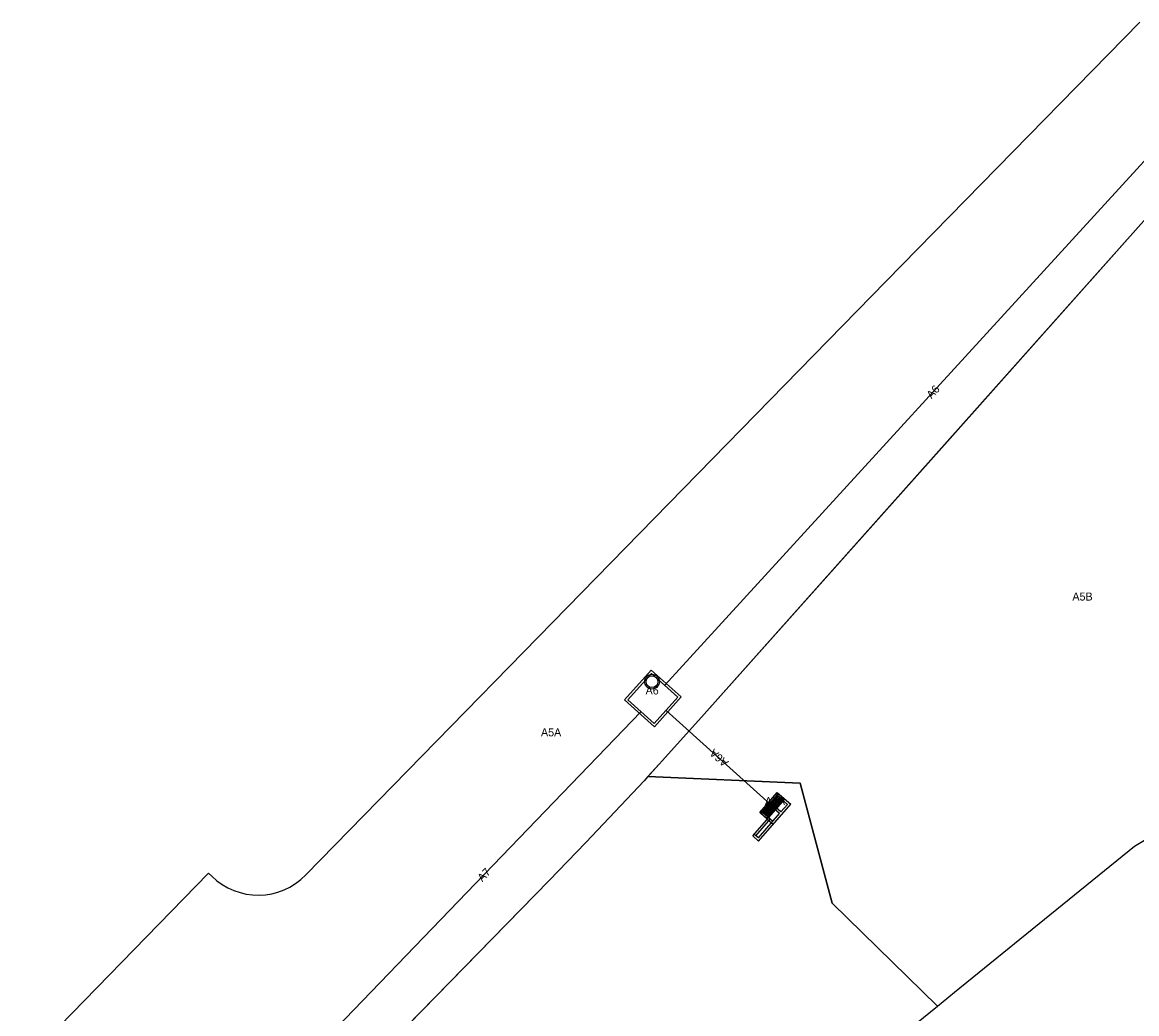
# Model space of a CAD drawing. Extents: x 2252703 to 2264864, y 13787568 to 13790989.
# Drawn here: x 2253981.3 to 2254231.9, y 13789915.2 to 13790138.2 of the extents above; entities that cross this region are included whole.
import ezdxf

# ---------------------------------------------------------------- set-up
doc = ezdxf.new("R2010")
doc.units = 0
for name, color, linetype in [('D_BOXES_1', 7, 'Continuous'), ('D_DRAIN_MISC', 7, 'Continuous'), ('D_DRAIN_NOTES_1', 7, 'Continuous'), ('D_DRN_AREA_X', 7, 'Continuous'), ('D_INLET_1', 7, 'Continuous'), ('D_PIPES_1', 7, 'Continuous')]:
    doc.layers.add(name, color=color, linetype=linetype)

msp = doc.modelspace()

# ---------------------------------------------------------------- linework, layer by layer
at = {"layer": 'D_BOXES_1'}
for p, q in [((2254125.73, 13789989.12), (2254246.59, 13790121.36)), ((2254049.99, 13789910), (2254120.39, 13789983.17))]:
    msp.add_line(p, q, dxfattribs=at)
at = {"layer": 'D_DRAIN_MISC'}
for p, q in [((2254125.73, 13789989.12), (2254125.73, 13789989.12)), ((2254120.08, 13789988.81), (2254120.08, 13789988.81)), ((2254123.06, 13789986.14), (2254123.06, 13789986.14)), ((2254120.39, 13789983.17), (2254120.39, 13789983.17)), ((2254126.03, 13789983.47), (2254126.03, 13789983.47)), ((2254149.44, 13789962.4), (2254149.44, 13789962.4)), ((2254152.21, 13789963.3), (2254152.21, 13789963.3)), ((2254148.93, 13789959.53), (2254148.93, 13789959.53)), ((2254150.76, 13789961.25), (2254150.76, 13789961.25)), ((2254151.7, 13789960.43), (2254151.7, 13789960.43))]:
    msp.add_line(p, q, dxfattribs=at)
at = {"layer": 'D_DRN_AREA_X'}
for p, q in [((2254232.56, 13790138.24), (2254175.55, 13790079.98)), ((2254134.63, 13789982.58), (2254234.65, 13790094.92)), ((2254234.65, 13790094.92), (2254189.9, 13790044.65)), ((2254189.9, 13790044.65), (2254134.63, 13789982.58)), ((2254134.63, 13789982.58), (2254125.24, 13789972.22)), ((2254231.38, 13789952.91), (2254269.1, 13789975.9)), ((2254125.24, 13789972.22), (2254121.96, 13789968.61)), ((2254121.09, 13789967.64), (2254108.02, 13789953.74)), ((2254121.96, 13789968.61), (2254121.09, 13789967.64)), ((2254121.96, 13789968.61), (2254156.18, 13789967.12)), ((2254156.18, 13789967.12), (2254121.96, 13789968.61)), ((2254156.18, 13789967.12), (2254163.36, 13789940.11)), ((2254163.36, 13789940.11), (2254156.18, 13789967.12)), ((2254108.02, 13789953.74), (2254099.77, 13789945.21)), ((2254190.88, 13789920.06), (2254231.38, 13789952.91)), ((2254023.17, 13789946.84), (2253981.29, 13789903.85)), ((2254023.87, 13789946.16), (2254023.17, 13789946.84)), ((2254099.77, 13789945.21), (2254058.27, 13789902.74)), ((2254163.36, 13789940.11), (2254187.06, 13789916.96)), ((2254187.06, 13789916.96), (2254163.36, 13789940.11)), ((2254187.06, 13789916.96), (2254190.88, 13789920.06)), ((2254156.89, 13789892.48), (2254187.06, 13789916.96))]:
    msp.add_line(p, q, dxfattribs=at)
for points in [[(2254175.55, 13790079.98), (2254126.68, 13790029.98), (2254045.04, 13789946.44)], [(2254108.02, 13789953.74), (2254121.09, 13789967.64), (2254134.63, 13789982.58)], [(2254025.79, 13789869.5), (2254099.77, 13789945.21), (2254108.02, 13789953.74)]]:
    msp.add_lwpolyline(points, dxfattribs=at)
msp.add_arc((2254034.32, 13789956.92), 15, 225.8716, 315.6588, dxfattribs=at)
at = {"layer": 'D_INLET_1'}
for p, q in [((2254116.7, 13789985.8), (2254122.72, 13789992.5)), ((2254117.41, 13789985.84), (2254122.76, 13789991.79)), ((2254122.72, 13789992.5), (2254129.41, 13789986.48)), ((2254122.76, 13789991.79), (2254128.71, 13789986.44)), ((2254128.71, 13789986.44), (2254123.36, 13789980.49)), ((2254129.41, 13789986.48), (2254123.4, 13789979.79)), ((2254123.4, 13789979.79), (2254116.7, 13789985.8)), ((2254123.36, 13789980.49), (2254117.41, 13789985.84)), ((2254147.09, 13789960.46), (2254151.02, 13789964.99)), ((2254147.1, 13789960.46), (2254151.03, 13789964.99)), ((2254147.36, 13789960.77), (2254150.76, 13789964.68)), ((2254147.41, 13789960.18), (2254151.34, 13789964.72)), ((2254147.8, 13789960.51), (2254151.07, 13789964.29)), ((2254151.03, 13789964.47), (2254149.34, 13789962.51)), ((2254151.04, 13789964.4), (2254149.4, 13789962.51)), ((2254149.42, 13789962.52), (2254151.04, 13789964.38)), ((2254149.51, 13789962.66), (2254150.99, 13789964.37)), ((2254150.73, 13789963.86), (2254150.86, 13789964.02)), ((2254151.02, 13789963.61), (2254150.73, 13789963.86)), ((2254151, 13789964.43), (2254150.74, 13789964.66)), ((2254150.79, 13789964.69), (2254151.2, 13789964.69)), ((2254151.15, 13789963.77), (2254150.86, 13789964.02)), ((2254150.92, 13789964.09), (2254151.06, 13789964.24)), ((2254151.21, 13789963.84), (2254150.92, 13789964.09)), ((2254151.02, 13789964.99), (2254154.05, 13789962.37)), ((2254151.03, 13789964.47), (2254152.32, 13789963.35)), ((2254151.04, 13789964.4), (2254152.25, 13789963.35)), ((2254151.04, 13789964.38), (2254152.23, 13789963.35)), ((2254151.06, 13789964.24), (2254151.35, 13789963.99)), ((2254151.07, 13789964.43), (2254151.26, 13789964.66)), ((2254151.07, 13789964.29), (2254153.34, 13789962.32)), ((2254151.12, 13789964.39), (2254151.31, 13789964.61)), ((2254151.21, 13789963.84), (2254151.35, 13789963.99)), ((2254151.24, 13789964.67), (2254152.53, 13789963.55)), ((2254151.29, 13789963.77), (2254151.43, 13789963.92)), ((2254151.43, 13789963.92), (2254151.72, 13789963.67)), ((2254145.52, 13789955.21), (2254152.72, 13789963.52)), ((2254146.84, 13789954.06), (2254154.05, 13789962.37)), ((2254147.61, 13789960.53), (2254149.31, 13789962.48)), ((2254147.68, 13789960.53), (2254149.32, 13789962.42)), ((2254149.32, 13789962.4), (2254147.7, 13789960.53)), ((2254147.7, 13789960.58), (2254149.18, 13789962.29)), ((2254148.56, 13789961.36), (2254148.42, 13789961.2)), ((2254148.85, 13789961.11), (2254148.56, 13789961.36)), ((2254148.75, 13789961.58), (2254148.62, 13789961.43)), ((2254148.91, 13789961.18), (2254148.62, 13789961.43)), ((2254148.73, 13789959.17), (2254151.63, 13789962.51)), ((2254149.04, 13789961.33), (2254148.75, 13789961.58)), ((2254148.95, 13789961.81), (2254148.81, 13789961.65)), ((2254149.1, 13789961.4), (2254148.81, 13789961.65)), ((2254148.89, 13789959.47), (2254150.53, 13789961.37)), ((2254148.89, 13789959.49), (2254150.51, 13789961.36)), ((2254148.9, 13789959.41), (2254150.59, 13789961.37)), ((2254149.04, 13789961.33), (2254148.91, 13789961.18)), ((2254149.23, 13789961.56), (2254148.95, 13789961.81)), ((2254149.14, 13789962.03), (2254149.01, 13789961.88)), ((2254149.3, 13789961.63), (2254149.01, 13789961.88)), ((2254149.23, 13789961.56), (2254149.1, 13789961.4)), ((2254149.43, 13789961.78), (2254149.14, 13789962.03)), ((2254149.32, 13789961.49), (2254149.18, 13789961.33)), ((2254149.47, 13789961.08), (2254149.18, 13789961.33)), ((2254149.33, 13789962.26), (2254149.2, 13789962.1)), ((2254149.49, 13789961.85), (2254149.2, 13789962.1)), ((2254151.54, 13789960.24), (2254149.21, 13789962.26)), ((2254149.43, 13789961.78), (2254149.3, 13789961.63)), ((2254149.31, 13789962.48), (2254150.59, 13789961.37)), ((2254149.32, 13789962.42), (2254150.53, 13789961.37)), ((2254149.32, 13789962.4), (2254150.51, 13789961.36)), ((2254149.61, 13789961.23), (2254149.32, 13789961.49)), ((2254149.33, 13789962.26), (2254149.62, 13789962.01)), ((2254149.34, 13789962.51), (2254150.62, 13789961.4)), ((2254149.51, 13789961.71), (2254149.38, 13789961.56)), ((2254149.67, 13789961.3), (2254149.38, 13789961.56)), ((2254149.4, 13789962.51), (2254150.61, 13789961.46)), ((2254149.42, 13789962.52), (2254150.61, 13789961.48)), ((2254149.62, 13789962.01), (2254149.49, 13789961.85)), ((2254149.8, 13789961.46), (2254149.51, 13789961.71)), ((2254151.87, 13789960.62), (2254149.54, 13789962.64)), ((2254149.56, 13789962.52), (2254149.69, 13789962.67)), ((2254149.56, 13789962.52), (2254149.85, 13789962.27)), ((2254149.71, 13789961.94), (2254149.57, 13789961.78)), ((2254149.86, 13789961.53), (2254149.57, 13789961.78)), ((2254149.8, 13789961.46), (2254149.67, 13789961.3)), ((2254149.98, 13789962.42), (2254149.69, 13789962.67)), ((2254149.71, 13789961.94), (2254150, 13789961.68)), ((2254149.88, 13789961.39), (2254149.75, 13789961.23)), ((2254149.76, 13789962.74), (2254149.89, 13789962.9)), ((2254150.04, 13789962.49), (2254149.76, 13789962.74)), ((2254149.85, 13789962.27), (2254149.98, 13789962.42)), ((2254150, 13789961.68), (2254149.86, 13789961.53)), ((2254150.17, 13789961.14), (2254149.88, 13789961.39)), ((2254150.18, 13789962.64), (2254149.89, 13789962.9)), ((2254149.93, 13789962.2), (2254150.06, 13789962.35)), ((2254149.93, 13789962.2), (2254150.22, 13789961.94)), ((2254150.08, 13789961.61), (2254149.94, 13789961.46)), ((2254150.23, 13789961.21), (2254149.94, 13789961.46)), ((2254149.95, 13789962.97), (2254150.08, 13789963.12)), ((2254150.24, 13789962.71), (2254149.95, 13789962.97)), ((2254150.04, 13789962.49), (2254150.18, 13789962.64)), ((2254150.36, 13789962.1), (2254150.06, 13789962.35)), ((2254150.37, 13789962.87), (2254150.08, 13789963.12)), ((2254150.08, 13789961.61), (2254150.37, 13789961.36)), ((2254150.13, 13789962.42), (2254150.26, 13789962.57)), ((2254150.42, 13789962.17), (2254150.13, 13789962.42)), ((2254150.14, 13789963.19), (2254150.28, 13789963.34)), ((2254150.43, 13789962.94), (2254150.14, 13789963.19)), ((2254150.22, 13789961.94), (2254150.36, 13789962.1)), ((2254150.23, 13789961.21), (2254150.37, 13789961.36)), ((2254150.24, 13789962.71), (2254150.37, 13789962.87)), ((2254150.55, 13789962.32), (2254150.26, 13789962.57)), ((2254150.57, 13789963.09), (2254150.28, 13789963.34)), ((2254150.3, 13789961.87), (2254150.44, 13789962.03)), ((2254150.3, 13789961.87), (2254150.59, 13789961.62)), ((2254150.32, 13789962.64), (2254150.45, 13789962.8)), ((2254150.61, 13789962.39), (2254150.32, 13789962.64)), ((2254150.34, 13789963.42), (2254150.47, 13789963.57)), ((2254150.63, 13789963.16), (2254150.34, 13789963.42)), ((2254150.42, 13789962.17), (2254150.55, 13789962.32)), ((2254150.43, 13789962.94), (2254150.57, 13789963.09)), ((2254150.73, 13789961.77), (2254150.44, 13789962.03)), ((2254150.75, 13789962.54), (2254150.45, 13789962.8)), ((2254150.76, 13789963.32), (2254150.47, 13789963.57)), ((2254150.5, 13789962.1), (2254150.63, 13789962.25)), ((2254150.79, 13789961.85), (2254150.5, 13789962.1)), ((2254150.52, 13789962.87), (2254150.65, 13789963.02)), ((2254150.81, 13789962.62), (2254150.52, 13789962.87)), ((2254150.53, 13789963.64), (2254150.67, 13789963.79)), ((2254150.82, 13789963.39), (2254150.53, 13789963.64)), ((2254150.73, 13789961.77), (2254150.59, 13789961.62)), ((2254152.25, 13789963.35), (2254150.61, 13789961.46)), ((2254152.23, 13789963.35), (2254150.61, 13789961.48)), ((2254150.61, 13789962.39), (2254150.75, 13789962.54)), ((2254152.32, 13789963.35), (2254150.62, 13789961.4)), ((2254150.63, 13789963.16), (2254150.76, 13789963.32)), ((2254150.92, 13789962), (2254150.63, 13789962.25)), ((2254150.94, 13789962.77), (2254150.65, 13789963.02)), ((2254150.96, 13789963.54), (2254150.67, 13789963.79)), ((2254150.69, 13789962.32), (2254150.83, 13789962.47)), ((2254150.98, 13789962.07), (2254150.69, 13789962.32)), ((2254150.71, 13789963.09), (2254150.84, 13789963.25)), ((2254151, 13789962.84), (2254150.71, 13789963.09)), ((2254150.92, 13789962), (2254150.79, 13789961.85)), ((2254150.81, 13789962.62), (2254150.94, 13789962.77)), ((2254150.82, 13789963.39), (2254150.96, 13789963.54)), ((2254151.12, 13789962.22), (2254150.83, 13789962.47)), ((2254151.14, 13789962.99), (2254150.84, 13789963.25)), ((2254150.89, 13789962.55), (2254151.02, 13789962.7)), ((2254151.18, 13789962.29), (2254150.89, 13789962.55)), ((2254150.91, 13789963.32), (2254151.04, 13789963.47)), ((2254151.2, 13789963.06), (2254150.91, 13789963.32)), ((2254151.12, 13789962.22), (2254150.98, 13789962.07)), ((2254151, 13789962.84), (2254151.14, 13789962.99)), ((2254151.02, 13789963.61), (2254151.15, 13789963.77)), ((2254151.31, 13789962.45), (2254151.02, 13789962.7)), ((2254151.33, 13789963.22), (2254151.04, 13789963.47)), ((2254151.08, 13789962.77), (2254151.22, 13789962.92)), ((2254151.37, 13789962.52), (2254151.08, 13789962.77)), ((2254151.1, 13789963.54), (2254151.23, 13789963.7)), ((2254151.39, 13789963.29), (2254151.1, 13789963.54)), ((2254151.31, 13789962.45), (2254151.18, 13789962.29)), ((2254151.2, 13789963.06), (2254151.33, 13789963.22)), ((2254151.51, 13789962.67), (2254151.22, 13789962.92)), ((2254151.53, 13789963.44), (2254151.23, 13789963.7)), ((2254151.28, 13789962.99), (2254151.41, 13789963.15)), ((2254151.57, 13789962.74), (2254151.28, 13789962.99)), ((2254151.59, 13789963.51), (2254151.29, 13789963.77)), ((2254151.51, 13789962.67), (2254151.37, 13789962.52)), ((2254151.39, 13789963.29), (2254151.53, 13789963.44)), ((2254151.7, 13789962.9), (2254151.41, 13789963.15)), ((2254151.47, 13789963.22), (2254151.61, 13789963.37)), ((2254151.76, 13789962.97), (2254151.47, 13789963.22)), ((2254151.7, 13789962.9), (2254151.57, 13789962.74)), ((2254151.59, 13789963.51), (2254151.72, 13789963.67)), ((2254151.9, 13789963.12), (2254151.61, 13789963.37)), ((2254151.63, 13789962.51), (2254152.53, 13789963.55)), ((2254151.67, 13789963.44), (2254151.8, 13789963.6)), ((2254151.96, 13789963.19), (2254151.67, 13789963.44)), ((2254151.9, 13789963.12), (2254151.76, 13789962.97)), ((2254151.8, 13789963.6), (2254152.09, 13789963.35)), ((2254151.87, 13789960.62), (2254153.34, 13789962.32)), ((2254152.09, 13789963.35), (2254151.96, 13789963.19)), ((2254152.23, 13789963.43), (2254152.42, 13789963.65)), ((2254152.28, 13789963.38), (2254152.47, 13789963.6)), ((2254146.22, 13789955.26), (2254149.5, 13789959.03)), ((2254146.79, 13789954.77), (2254151.54, 13789960.24)), ((2254147.09, 13789960.46), (2254148.79, 13789958.98)), ((2254147.35, 13789960.73), (2254147.42, 13789960.32)), ((2254147.64, 13789960.56), (2254147.38, 13789960.78)), ((2254147.44, 13789960.29), (2254148.73, 13789959.17)), ((2254147.65, 13789960.49), (2254147.46, 13789960.27)), ((2254147.7, 13789960.45), (2254147.51, 13789960.23)), ((2254147.61, 13789960.53), (2254148.9, 13789959.41)), ((2254147.68, 13789960.53), (2254148.89, 13789959.47)), ((2254147.7, 13789960.53), (2254148.89, 13789959.49)), ((2254147.8, 13789960.51), (2254150.06, 13789958.54)), ((2254147.97, 13789960.68), (2254147.84, 13789960.53)), ((2254147.84, 13789960.53), (2254148.13, 13789960.28)), ((2254148.26, 13789960.43), (2254147.97, 13789960.68)), ((2254148.17, 13789960.91), (2254148.03, 13789960.76)), ((2254148.32, 13789960.5), (2254148.03, 13789960.76)), ((2254148.26, 13789960.43), (2254148.13, 13789960.28)), ((2254148.46, 13789960.66), (2254148.17, 13789960.91)), ((2254148.34, 13789960.36), (2254148.21, 13789960.21)), ((2254148.21, 13789960.21), (2254148.5, 13789959.96)), ((2254148.36, 13789961.13), (2254148.23, 13789960.98)), ((2254148.52, 13789960.73), (2254148.23, 13789960.98)), ((2254148.46, 13789960.66), (2254148.32, 13789960.5)), ((2254148.63, 13789960.11), (2254148.34, 13789960.36)), ((2254148.65, 13789960.88), (2254148.36, 13789961.13)), ((2254148.54, 13789960.59), (2254148.4, 13789960.43)), ((2254148.69, 13789960.18), (2254148.4, 13789960.43)), ((2254148.71, 13789960.95), (2254148.42, 13789961.2)), ((2254148.63, 13789960.11), (2254148.5, 13789959.96)), ((2254148.65, 13789960.88), (2254148.52, 13789960.73)), ((2254148.83, 13789960.33), (2254148.54, 13789960.59)), ((2254148.71, 13789960.04), (2254148.58, 13789959.89)), ((2254148.58, 13789959.89), (2254148.87, 13789959.63)), ((2254148.73, 13789960.81), (2254148.6, 13789960.66)), ((2254148.89, 13789960.41), (2254148.6, 13789960.66)), ((2254148.81, 13789959.49), (2254148.62, 13789959.27)), ((2254148.86, 13789959.44), (2254148.67, 13789959.22)), ((2254148.83, 13789960.33), (2254148.69, 13789960.18)), ((2254148.85, 13789961.11), (2254148.71, 13789960.95)), ((2254149, 13789959.79), (2254148.71, 13789960.04)), ((2254149.02, 13789960.56), (2254148.73, 13789960.81)), ((2254148.91, 13789960.26), (2254148.78, 13789960.11)), ((2254149.07, 13789959.86), (2254148.78, 13789960.11)), ((2254148.93, 13789961.04), (2254148.79, 13789960.88)), ((2254149.08, 13789960.63), (2254148.79, 13789960.88)), ((2254148.79, 13789958.98), (2254150.11, 13789957.84)), ((2254148.87, 13789959.63), (2254149, 13789959.79)), ((2254149.02, 13789960.56), (2254148.89, 13789960.41)), ((2254149.2, 13789960.01), (2254148.91, 13789960.26)), ((2254149.22, 13789960.78), (2254148.93, 13789961.04)), ((2254149.1, 13789960.49), (2254148.97, 13789960.34)), ((2254149.26, 13789960.08), (2254148.97, 13789960.34)), ((2254149.12, 13789961.26), (2254148.99, 13789961.11)), ((2254149.28, 13789960.85), (2254148.99, 13789961.11)), ((2254149.07, 13789959.86), (2254149.2, 13789960.01)), ((2254149.22, 13789960.78), (2254149.08, 13789960.63)), ((2254149.39, 13789960.24), (2254149.1, 13789960.49)), ((2254149.41, 13789961.01), (2254149.12, 13789961.26)), ((2254149.3, 13789960.71), (2254149.17, 13789960.56)), ((2254149.46, 13789960.31), (2254149.17, 13789960.56)), ((2254149.26, 13789960.08), (2254149.39, 13789960.24)), ((2254149.41, 13789961.01), (2254149.28, 13789960.85)), ((2254149.59, 13789960.46), (2254149.3, 13789960.71)), ((2254149.49, 13789960.94), (2254149.36, 13789960.78)), ((2254149.65, 13789960.53), (2254149.36, 13789960.78)), ((2254149.46, 13789960.31), (2254149.59, 13789960.46)), ((2254149.61, 13789961.23), (2254149.47, 13789961.08)), ((2254149.78, 13789960.69), (2254149.49, 13789960.94)), ((2254149.69, 13789961.16), (2254149.56, 13789961.01)), ((2254149.84, 13789960.76), (2254149.56, 13789961.01)), ((2254149.65, 13789960.53), (2254149.78, 13789960.69)), ((2254149.98, 13789960.91), (2254149.69, 13789961.16)), ((2254150.04, 13789960.98), (2254149.75, 13789961.23)), ((2254149.84, 13789960.76), (2254149.98, 13789960.91)), ((2254150.04, 13789960.98), (2254150.17, 13789961.14)), ((2254146.84, 13789954.06), (2254145.52, 13789955.21)), ((2254146.79, 13789954.77), (2254145.84, 13789955.58))]:
    msp.add_line(p, q, dxfattribs=at)
for radius in [1.67, 1.33]:
    msp.add_circle((2254122.86, 13789989.91), radius, dxfattribs=at)
for centre, start_param, end_param in [((2254150.79, 13789964.65), 5.480245, 6.283185), ((2254151.21, 13789964.64), 4.712389, 5.480245), ((2254147.4, 13789960.73), 0, 0.80294), ((2254147.46, 13789960.32), 0.80294, 1.570796)]:
    msp.add_ellipse(centre, major_axis=(-0.0359, 0.0312), ratio=0.877193, start_param=start_param, end_param=end_param, dxfattribs=at)
at = {"layer": 'D_PIPES_1'}
msp.add_line((2254149.44, 13789962.4), (2254126.03, 13789983.47), dxfattribs=at)

# ---------------------------------------------------------------- texts
at = {"layer": 'D_DRAIN_NOTES_1'}
for s, rotation, p in [('A6', 47.5752, (2254185.73, 13790053.43)), ('A6A', 138.0004, (2254140.21, 13789971.91)), ('A7', 46.1022, (2254084.72, 13789944.81))]:
    msp.add_text(s, height=1.8, rotation=rotation, dxfattribs=at).set_placement(p)
for s, p in [('A5B', (2254217.39, 13790008.17)), ('A6', (2254121.43, 13789987.04)), ('A5A', (2254097.91, 13789977.63)), ('A6A', (2254148.24, 13789962.15))]:
    msp.add_text(s, height=1.8, dxfattribs=at).set_placement(p)

doc.saveas('drawing.dxf')
